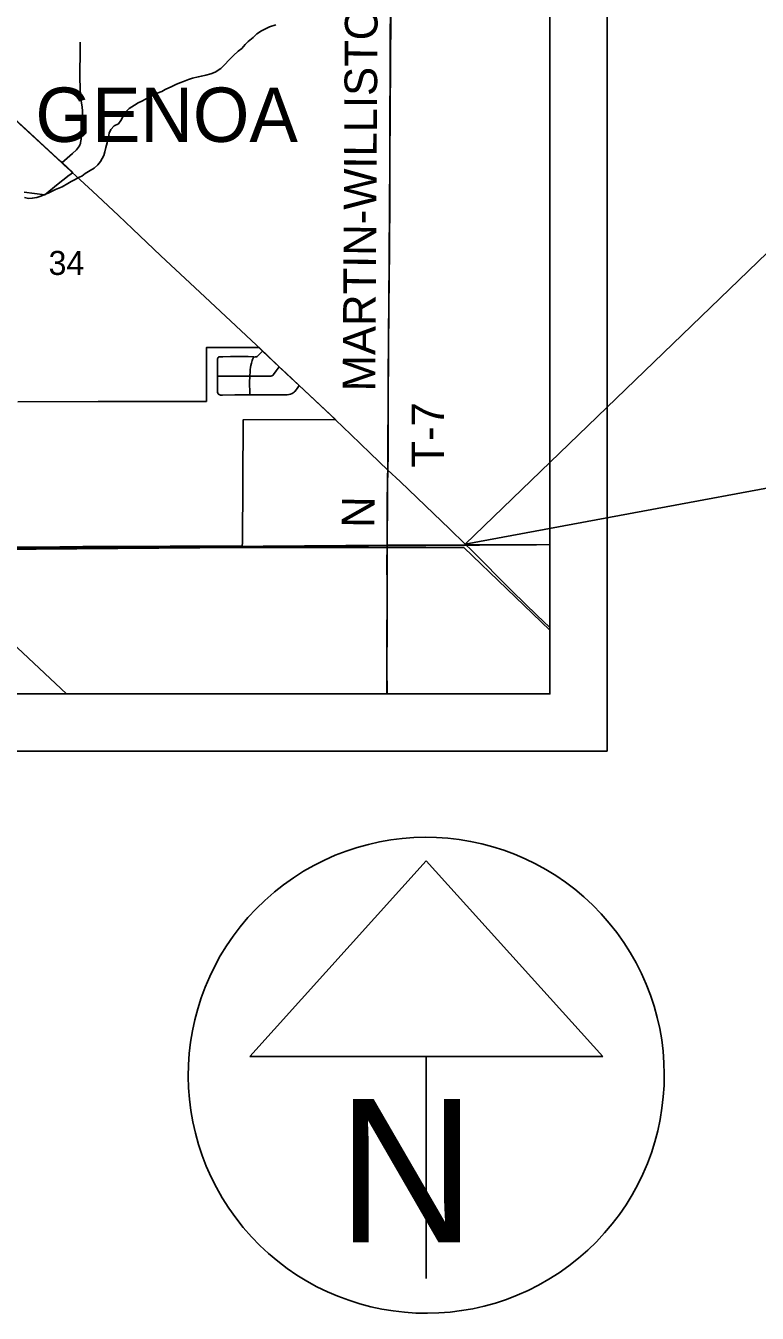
# Model space of a CAD drawing. Extents: x 0 to 34, y 0 to 22.
# Drawn here: x 7.987 to 9.261, y 13.021 to 15.265 of the extents above; entities that cross this region are included whole.
import ezdxf

# ---------------------------------------------------------------- set-up
doc = ezdxf.new("R2010")
doc.units = 0
for name, color, linetype in [('Default', 7, 'Continuous'), ('GM_X_City_Street', 7, 'Continuous'), ('GM_X_Corporation_Text', 7, 'Continuous'), ('GM_X_Interstate_Route', 7, 'Continuous'), ('GM_X_Minor_River', 7, 'Continuous'), ('GM_X_Rail_Line', 7, 'Continuous'), ('GM_X_Section', 7, 'Continuous'), ('GM_X_Section_Text', 7, 'Continuous'), ('GM_X_State_Route', 7, 'Continuous'), ('GM_X_Township_Road', 7, 'Continuous'), ('GM_X_Township_Road_Text', 7, 'Continuous'), ('SH_Data', 7, 'Continuous'), ('SH_Text', 7, 'Continuous')]:
    doc.layers.add(name, color=color, linetype=linetype)

msp = doc.modelspace()

# ---------------------------------------------------------------- linework, layer by layer
at = {"layer": 'Default'}
for points in [[(8.9, 14.3602), (8.9, 15.3679), (8.6234, 15.3665), (8.6163, 14.3591)], [(7.6078, 14.1), (8.6158, 14.1), (8.6163, 14.3591), (7.6069, 14.3511)], [(8.6158, 14.1), (8.9, 14.1), (8.9, 14.3602), (8.6163, 14.3591)]]:
    msp.add_lwpolyline(points, close=True, dxfattribs=at)
for points in [[(7.9837, 14.9746), (8.0196, 14.9699), (8.0403, 14.9864), (8.0624, 15.0038), (8.0649, 15.0058), (8.0684, 15.0086), (8.0499, 15.0259), (8.0477, 15.028), (8.0465, 15.0291), (8.0414, 15.0339), (8.0178, 15.0554), (8.0106, 15.0619), (7.9941, 15.0771), (7.9592, 15.1092)], [(7.9632, 14.3555), (8.0461, 14.3565), (8.0863, 14.3567), (8.1099, 14.3568), (8.113, 14.3568), (8.3639, 14.3579), (8.364, 14.3631), (8.3656, 14.5778), (8.5264, 14.5781), (8.4627, 14.6378), (8.4407, 14.6585), (8.4278, 14.6708), (8.3933, 14.7037), (8.3905, 14.7038), (8.3016, 14.7039), (8.3014, 14.6099), (8.1127, 14.6096), (7.9728, 14.609)]]:
    msp.add_lwpolyline(points, dxfattribs=at)
at = {"layer": 'GM_X_City_Street'}
for points in [[(8.3207, 14.6536), (8.3209, 14.6825), (8.3209, 14.6841), (8.3211, 14.685), (8.3212, 14.6857), (8.3216, 14.6863), (8.3221, 14.6867), (8.3226, 14.687), (8.3234, 14.6873), (8.3242, 14.6874), (8.33, 14.6875), (8.3435, 14.6879), (8.3584, 14.688), (8.3741, 14.6878), (8.382, 14.6873), (8.3835, 14.6872)], [(8.377, 14.6536), (8.3771, 14.6554), (8.3774, 14.6601), (8.3779, 14.665), (8.3784, 14.6692), (8.379, 14.6725), (8.3799, 14.6764), (8.3811, 14.6808), (8.3818, 14.6829), (8.3828, 14.6854), (8.3835, 14.6872)], [(8.3835, 14.6872), (8.385, 14.6871), (8.3872, 14.6872), (8.3887, 14.6876), (8.39, 14.6883), (8.391, 14.6892), (8.3932, 14.6914), (8.3994, 14.6976)], [(8.3768, 14.6214), (8.351, 14.621), (8.3295, 14.6206), (8.3278, 14.6206), (8.3261, 14.6208), (8.3245, 14.6212), (8.3235, 14.6216), (8.3225, 14.6222), (8.3219, 14.6229), (8.3211, 14.6242), (8.3207, 14.6256), (8.3205, 14.6273), (8.3205, 14.6298), (8.3206, 14.6424), (8.3207, 14.6536)], [(8.3207, 14.6536), (8.3357, 14.6536), (8.3573, 14.6535), (8.377, 14.6536)], [(8.3768, 14.6214), (8.3768, 14.6241), (8.3767, 14.6426), (8.377, 14.6536)], [(8.377, 14.6536), (8.3911, 14.6537), (8.4029, 14.6535), (8.4115, 14.6536), (8.4141, 14.6539), (8.415, 14.6541), (8.4159, 14.6545), (8.4167, 14.6549), (8.4175, 14.6556), (8.4182, 14.6565), (8.4231, 14.6633), (8.4281, 14.6702)], [(8.4629, 14.6373), (8.4595, 14.6324), (8.4579, 14.6301), (8.4556, 14.6271), (8.4542, 14.6258), (8.4528, 14.6247), (8.451, 14.6235), (8.4481, 14.6224), (8.4451, 14.6217), (8.442, 14.6214), (8.4328, 14.6211), (8.4141, 14.6213), (8.3807, 14.6215), (8.3768, 14.6214)]]:
    msp.add_lwpolyline(points, dxfattribs=at)
at = {"layer": 'GM_X_Interstate_Route'}
msp.add_lwpolyline([(4.7033, 15.2872), (4.704, 15.2372), (4.7044, 15.1626), (4.7047, 15.0849), (4.7047, 15.0383), (4.7052, 14.9668), (4.7054, 14.8953), (4.7055, 14.7399), (4.705, 14.6903), (4.7046, 14.5938), (4.705, 14.4959), (4.7052, 14.4725), (4.7052, 14.4414), (4.7052, 14.3917), (4.705, 14.347), (4.7049, 14.3358), (4.7038, 14.2643), (4.7028, 14.1744), (4.7022, 14.1275), (4.7021, 14.1056), (4.7021, 14.1), (8.9, 14.1), (8.9, 17.3895)], dxfattribs=at)
at = {"layer": 'GM_X_Minor_River'}
for points in [[(8.4221, 15.2659), (8.4115, 15.2625), (8.4032, 15.2587), (8.3971, 15.2556), (8.3895, 15.2503), (8.3827, 15.2443), (8.3744, 15.2371), (8.3687, 15.2317)], [(8.3687, 15.2317), (8.363, 15.2249), (8.3565, 15.2204), (8.3486, 15.2128), (8.3417, 15.2056), (8.3323, 15.1961), (8.3266, 15.19), (8.3167, 15.1839), (8.3091, 15.1805), (8.3004, 15.1782), (8.2928, 15.1767), (8.2872, 15.1752), (8.2769, 15.1729), (8.2701, 15.1707), (8.2614, 15.1676), (8.2549, 15.165), (8.2481, 15.1623), (8.2409, 15.1589), (8.2295, 15.1536), (8.2235, 15.1502), (8.2155, 15.1472), (8.2087, 15.1438), (8.2022, 15.14), (8.1954, 15.1366), (8.1886, 15.1328), (8.1825, 15.1301), (8.1761, 15.1263), (8.167, 15.1202), (8.1594, 15.1127), (8.1556, 15.1058), (8.1522, 15.0994), (8.148, 15.0937), (8.1404, 15.0903), (8.1351, 15.0834), (8.1321, 15.0774), (8.1306, 15.0701), (8.1287, 15.0607), (8.1264, 15.0523), (8.1245, 15.0447), (8.1226, 15.0386), (8.1169, 15.028), (8.112, 15.0219), (8.1055, 15.0162), (8.0987, 15.0125), (8.09, 15.0068), (8.0843, 15.0022), (8.0782, 14.9999), (8.0725, 14.9965), (8.0657, 14.9931), (8.06, 14.9897), (8.0498, 14.984), (8.0384, 14.9791), (8.0323, 14.976), (8.0259, 14.973), (8.0198, 14.9704), (8.0126, 14.9673), (8.0058, 14.9654), (7.9978, 14.9639), (7.9914, 14.9635), (7.9846, 14.9654)]]:
    msp.add_lwpolyline(points, dxfattribs=at)
at = {"layer": 'GM_X_Rail_Line'}
for points in [[(7.6203, 15.4116), (7.6888, 15.3547), (7.6772, 14.5433), (7.683, 14.4528), (7.7895, 14.3507), (8.3611, 14.3552), (8.75, 14.3552), (8.9, 14.2113)], [(7.6056, 14.5217), (7.7617, 14.3728), (7.8669, 14.2782), (8.0578, 14.1)]]:
    msp.add_lwpolyline(points, dxfattribs=at)
at = {"layer": 'GM_X_Section'}
msp.add_lwpolyline([(8.6234, 15.3665), (8.6163, 14.3591), (7.6069, 14.3511), (7.6191, 15.3755)], close=True, dxfattribs=at)
at = {"layer": 'GM_X_State_Route'}
for points in [[(8.0496, 15.0254), (7.9453, 15.1216), (7.9423, 15.1241)], [(7.9423, 15.1241), (7.9453, 15.1216), (8.0496, 15.0254)], [(8.0671, 15.0094), (8.0648, 15.0115), (8.0531, 15.0222), (8.0496, 15.0254)], [(8.0496, 15.0254), (8.0531, 15.0222), (8.0648, 15.0115), (8.0671, 15.0094)], [(8.3886, 14.7078), (8.2901, 14.8002), (8.2222, 14.8637), (8.1726, 14.9103), (8.1479, 14.9338), (8.1026, 14.976), (8.0747, 15.0025), (8.0671, 15.0094)], [(8.0671, 15.0094), (8.0747, 15.0025), (8.1026, 14.976), (8.1479, 14.9338), (8.1726, 14.9103), (8.2222, 14.8637), (8.2901, 14.8002), (8.3886, 14.7078)], [(8.5191, 14.5846), (8.4629, 14.6373), (8.4409, 14.6579), (8.4281, 14.6702), (8.3994, 14.6976), (8.3935, 14.7032), (8.3915, 14.705), (8.3886, 14.7078)], [(8.3886, 14.7078), (8.3915, 14.705), (8.3935, 14.7032), (8.3994, 14.6976), (8.4281, 14.6702), (8.4409, 14.6579), (8.4629, 14.6373), (8.5191, 14.5846)], [(8.754, 14.3593), (8.7521, 14.3612), (8.7251, 14.3875), (8.6833, 14.4276), (8.6389, 14.4699), (8.6178, 14.4901), (8.587, 14.5197), (8.5528, 14.5519), (8.5266, 14.5776), (8.5235, 14.5805), (8.5191, 14.5846)], [(8.5191, 14.5846), (8.5235, 14.5805), (8.5266, 14.5776), (8.5528, 14.5519), (8.587, 14.5197), (8.6178, 14.4901), (8.6389, 14.4699), (8.6833, 14.4276), (8.7251, 14.3875), (8.7521, 14.3612), (8.754, 14.3593)], [(7.9634, 14.3541), (8.0175, 14.3551), (8.0704, 14.3558), (8.1139, 14.3558), (8.1543, 14.3563), (8.3503, 14.3567), (8.3666, 14.3568)], [(8.3666, 14.3568), (8.5338, 14.3578), (8.5836, 14.3582), (8.6161, 14.3586), (8.6838, 14.3589), (8.754, 14.3593)], [(8.754, 14.3593), (8.777, 14.3595), (8.8765, 14.36), (8.9, 14.3603)], [(8.9, 14.2156), (8.8997, 14.2159), (8.877, 14.2371), (8.8348, 14.2784), (8.7615, 14.3524), (8.754, 14.3593)]]:
    msp.add_lwpolyline(points, dxfattribs=at)
at = {"layer": 'GM_X_Township_Road'}
for points in [[(8.6178, 14.4901), (8.6179, 14.5185), (8.618, 14.5651), (8.6181, 14.593), (8.6182, 14.6427), (8.6186, 14.7266), (8.6193, 14.7826), (8.6197, 14.8136), (8.6204, 14.882), (8.621, 14.9583), (8.6213, 15.0498), (8.6213, 15.121), (8.6217, 15.1647), (8.6216, 15.2082), (8.6219, 15.329), (8.6218, 15.3543), (8.622, 15.3639)], [(8.0496, 15.0254), (8.0542, 15.0294), (8.0682, 15.0417), (8.0748, 15.0481), (8.0769, 15.0504), (8.0787, 15.0527), (8.0802, 15.0553), (8.081, 15.0568), (8.0814, 15.058), (8.082, 15.0595), (8.0822, 15.0608), (8.0831, 15.0668), (8.0856, 15.0944), (8.0857, 15.1005), (8.0858, 15.1062), (8.0856, 15.1107), (8.0852, 15.1158), (8.0846, 15.123), (8.0838, 15.1296), (8.0831, 15.1343), (8.0817, 15.1432), (8.0811, 15.1555), (8.081, 15.1739), (8.0813, 15.2264), (8.0815, 15.2357)], [(8.6161, 14.3586), (8.6161, 14.3678), (8.6164, 14.4346), (8.6172, 14.4688), (8.6178, 14.4843), (8.6178, 14.4901)], [(8.6163, 14.1), (8.616, 14.1468), (8.6164, 14.2151), (8.6164, 14.2866), (8.6157, 14.3273), (8.6161, 14.3586)]]:
    msp.add_lwpolyline(points, dxfattribs=at)
at = {"layer": 'SH_Data'}
for p, q in [((9, 21), (9, 14)), ((8.9, 20.9), (8.9, 14.1)), ((2.1, 14.1), (8.9, 14.1)), ((2, 14), (9, 14)), ((8.6845, 13.8091), (8.3769, 13.4678)), ((8.9921, 13.4678), (8.6845, 13.8091)), ((8.3769, 13.4678), (8.9921, 13.4678)), ((8.6845, 13.4678), (8.6845, 13.0811)), ((8.6845, 13.4353), (8.6845, 13.4353)), ((8.6845, 13.4353), (8.6845, 13.4353))]:
    msp.add_line(p, q, dxfattribs=at)
msp.add_arc((8.6845, 13.4353), 0.4148, 129.7798, 129.7633, dxfattribs=at)
at = {"layer": 'SH_Text'}
msp.add_lwpolyline([(9.6402, 15.2179), (8.7521, 14.3612), (9.6402, 14.5261)], close=True, dxfattribs=at)

# ---------------------------------------------------------------- texts
at = {"layer": 'GM_X_Corporation_Text'}
msp.add_text('GENOA', height=0.0947, rotation=0, dxfattribs=at).set_placement((8.0034, 15.0621))
at = {"layer": 'GM_X_Section_Text'}
msp.add_text('34', height=0.04186, rotation=0, dxfattribs=at).set_placement((8.0263, 14.8302))
at = {"layer": 'GM_X_Township_Road_Text'}
for s, height, rotation, p in [('MARTIN-WILLISTON', 0.056818, 89.6475, (8.5956, 14.6271)), ('T-7', 0.05682, 90, (8.7156, 14.4943)), ('N', 0.0568, 89.4026, (8.5939, 14.3892))]:
    msp.add_text(s, height=height, rotation=rotation, dxfattribs=at).set_placement(p)
at = {"layer": 'SH_Data'}
msp.add_text('N', height=0.25, dxfattribs=at).set_placement((8.5292, 13.144))

doc.saveas('drawing.dxf')
